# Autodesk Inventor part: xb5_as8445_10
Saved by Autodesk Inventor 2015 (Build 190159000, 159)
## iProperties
Created: 2018-04
Part Number: xb5_as8445_10
Checked By: TraceParts S.A.
Material: Generic
Catalog Web Link: www.traceparts.com
Document SubType Name: Modeling
Designer: TraceParts
Density: 1 g/cm^3
Appearance: Default
Company: TraceParts S.A.
Author: TraceParts
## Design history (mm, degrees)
feature "xb5_as8445_10.ipt"
body "Solid1"
